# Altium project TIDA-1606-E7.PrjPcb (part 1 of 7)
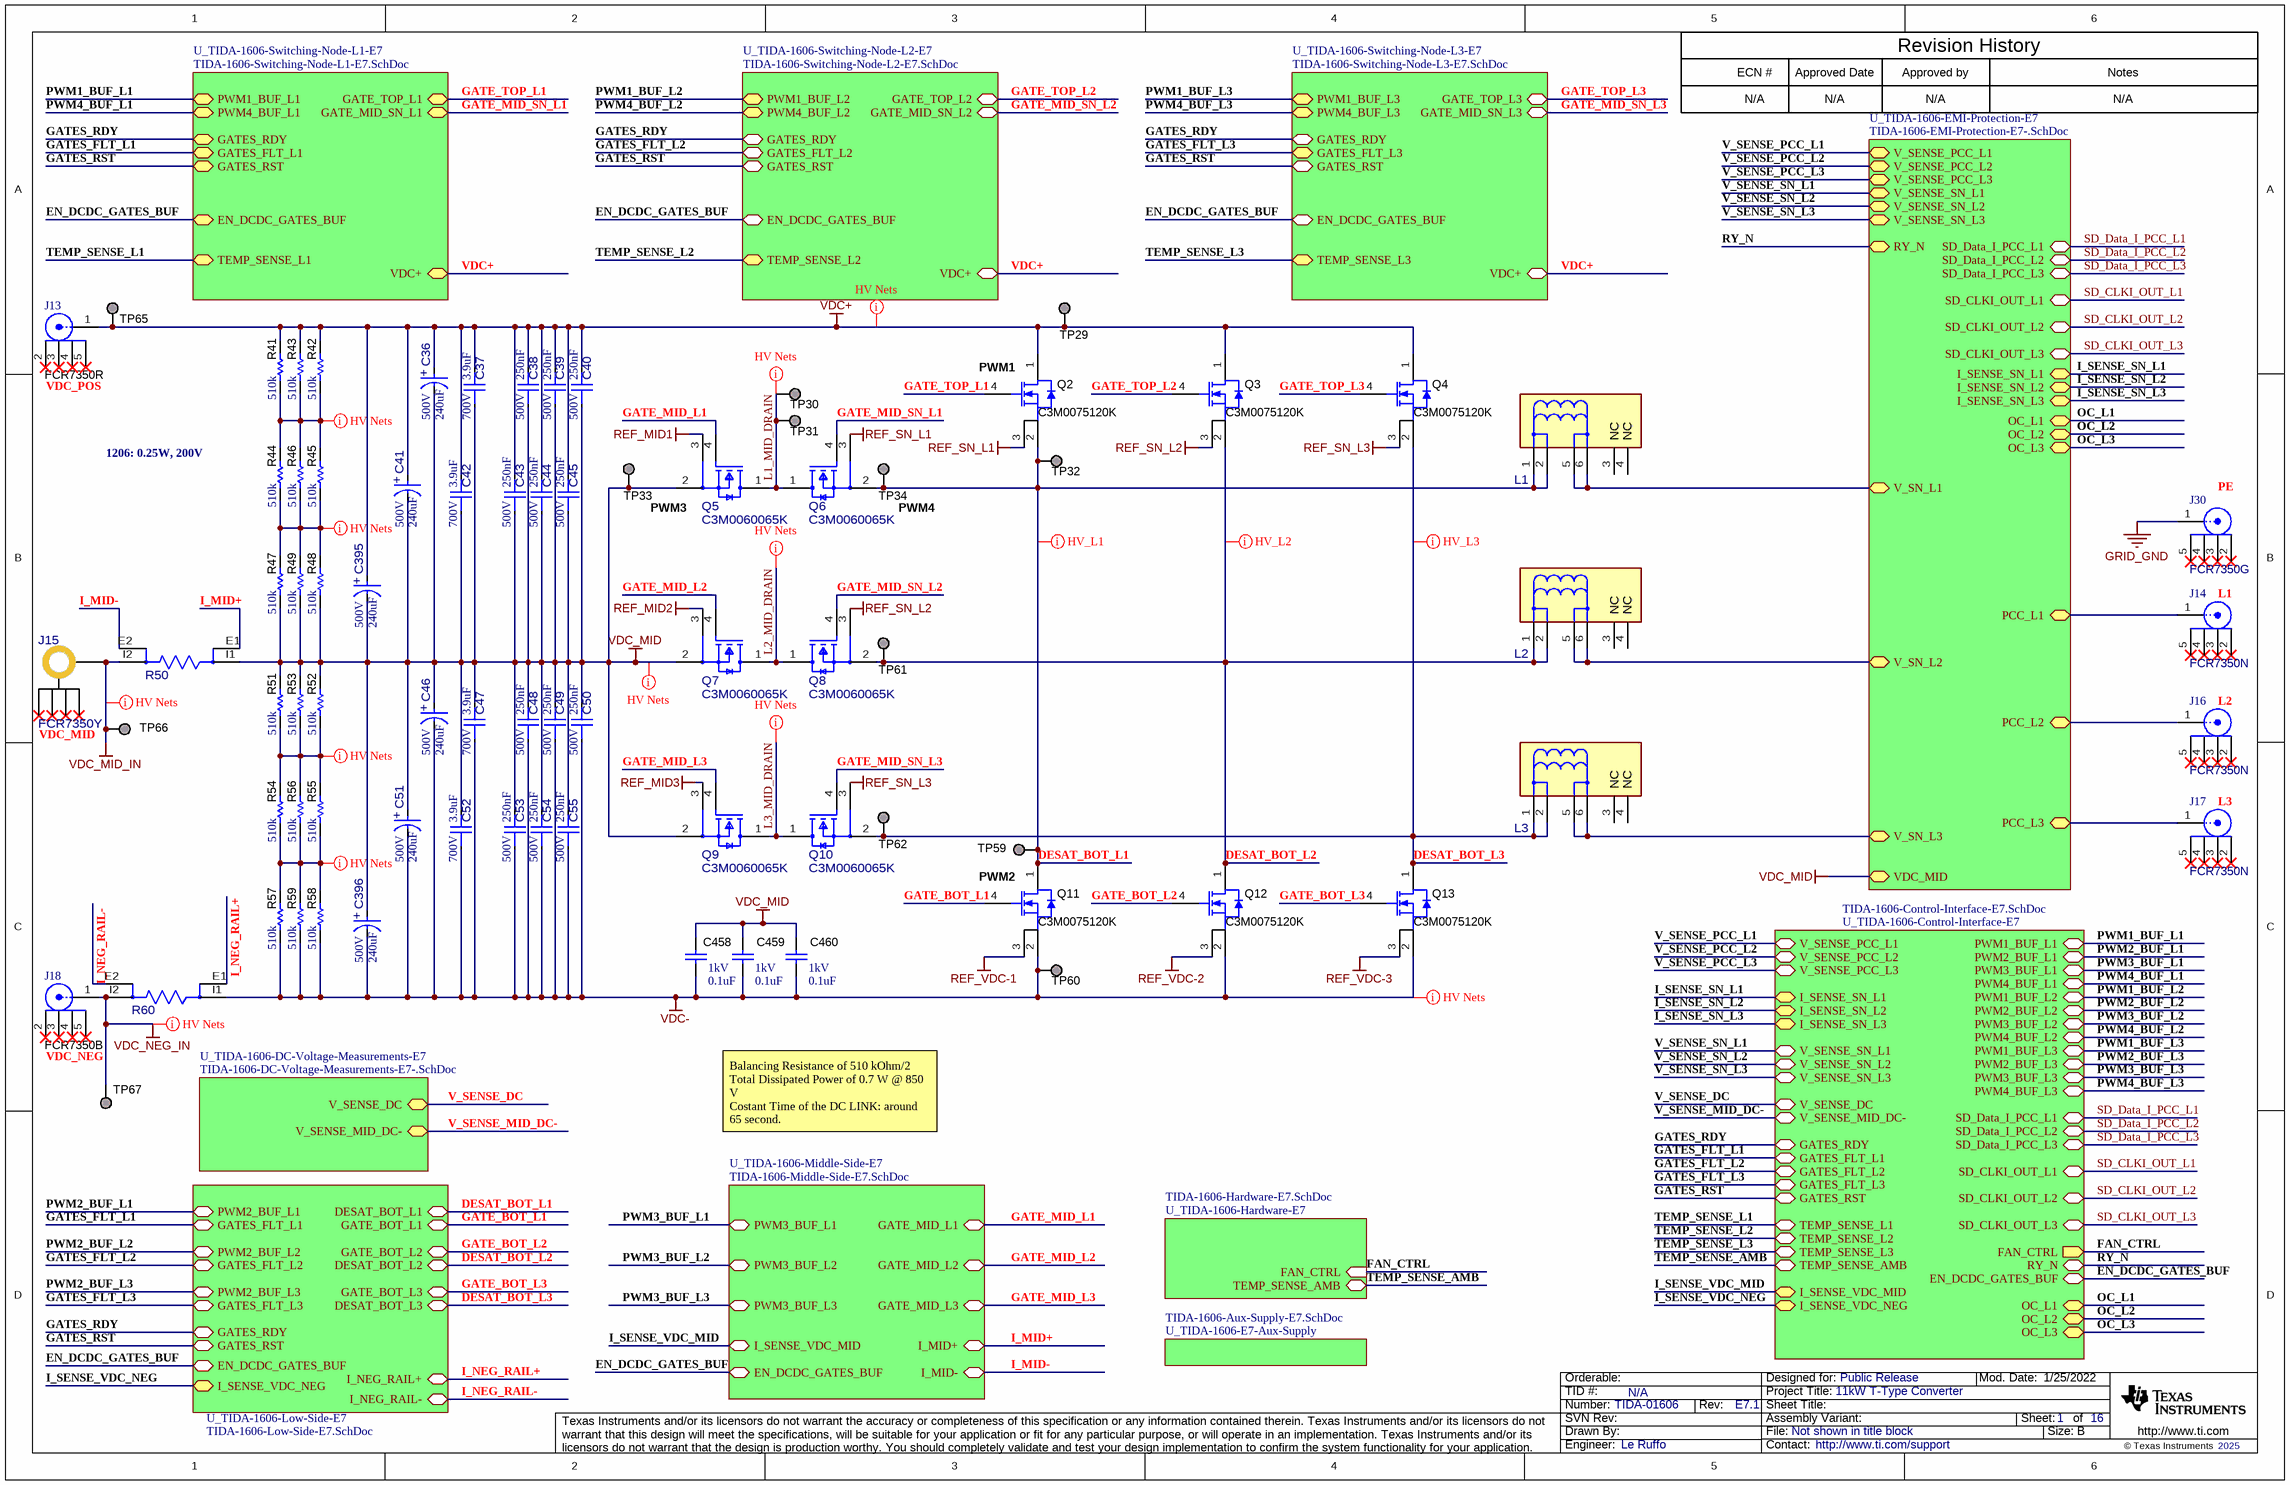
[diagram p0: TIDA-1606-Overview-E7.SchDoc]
TID: N/A; TechSupport: http://www.ti.com/support; SCH_Rev: E7.1; PRJ_Title: 11kW T-Type Converter; PRJ_Number: TIDA-01606; PRJ_Engineer: Le Ruffo; PRJ_Customer: Public Release; PCB_Rev: E7.1; PCB_Layout: Le Ruffo; CopyrightYear: 2025
16 sheets, 1283 parts. Net scope: hierarchical (ports join the sheet entries above them; power ports are global).
Board file: TIDA-1606-E7.PcbDoc
Sheets:
  TIDA-1606-Overview-E7.SchDoc
    U_TIDA-1606-EMI-Protection-E7 = TIDA-1606-EMI-Protection-E7-.SchDoc
      U_TIDA-1606-PCC-Current-Measurements-E7 = TIDA-1606-PCC-Current-Measurements-E7.SchDoc
      U_TIDA-1606-PCC-Voltage-Measurements-E7 = TIDA-1606-PCC-Voltage-Measurements-E7.SchDoc
      U_TIDA-1606-SW-Voltage-Measurements-E7 = TIDA-1606-SW-Voltage-Measurements-E7.SchDoc
      U_TIDA-1606-SW-Current-Measurements-E7 = TIDA-1606-SW-Current-Measurements-E7.SchDoc
    U_TIDA-1606-Switching-Node-L1-E7 = TIDA-1606-Switching-Node-L1-E7.SchDoc
    U_TIDA-1606-Switching-Node-L2-E7 = TIDA-1606-Switching-Node-L2-E7.SchDoc
    U_TIDA-1606-Switching-Node-L3-E7 = TIDA-1606-Switching-Node-L3-E7.SchDoc
    U_TIDA-1606-Low-Side-E7 = TIDA-1606-Low-Side-E7.SchDoc
    U_TIDA-1606-Middle-Side-E7 = TIDA-1606-Middle-Side-E7.SchDoc
    U_TIDA-1606-DC-Voltage-Measurements-E7 = TIDA-1606-DC-Voltage-Measurements-E7-.SchDoc
    U_TIDA-1606-Control-Interface-E7 = TIDA-1606-Control-Interface-E7.SchDoc
      U_TIDA-1606-CAN-Communication-E7 = TIDA-1606-CAN-Communication-E7.SchDoc
    U_TIDA-1606-E7-Aux-Supply = TIDA-1606-Aux-Supply-E7.SchDoc
    U_TIDA-1606-Hardware-E7 = TIDA-1606-Hardware-E7.SchDoc

## Sheet TIDA-1606-Overview-E7.SchDoc
size 431 x 279 mm; Date: Not shown in title block; ApprovedBy: Not shown in title block; CheckedBy: Not shown in title block; Author: Not shown in title block; CompanyName: Not shown in title block; Engineer: Not shown in title block; Organization: Not shown in title block; Address1: Not shown in title block; Address2: Not shown in title block; Address3: Not shown in title block; Address4: Not shown in title block; DocumentNumber: 1; Revision: Use project parameter SCH_Rev; SheetNumber: 1; SheetTotal: 16; PageSetup: Record=PageOptions¦CenterHorizontal=True¦CenterVertical=True¦PrintScale=1.00¦XCorrection=1.00¦YCorrection=1.00¦PrintKind=0¦BorderSize=5000000¦LeftOffset=0¦BottomOffset=0¦Orientation=2¦PaperLength=1000¦PaperWidth=1000¦Scale=100¦PaperSource=15¦PrintQuality=600¦MediaType=1¦DitherType=10¦PaperKind=Letter¦PrintScaleMode=1

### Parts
C36  VDC_V: 500V  ValueDisplayed: 240uF  [FP-ALA8DA241CD500_RADIAL-MFG]  (hidden comment: ALA8DA241CD500)
C37  ValueDisplayed: 3.9uF  VDC_V: 700V  [FP-B32774H8395K000_RADIAL-MFG]  (hidden comment: B32774H8395K000)
C38  ValueDisplayed: 250nF  VDC_V: 500V  [FP-B58043E5254M052_2220-MFG]  (hidden comment: B58043E5254M052)
C39  ValueDisplayed: 250nF  VDC_V: 500V  [FP-B58043E5254M052_2220-MFG]  (hidden comment: B58043E5254M052)
C40  ValueDisplayed: 250nF  VDC_V: 500V  [FP-B58043E5254M052_2220-MFG]  (hidden comment: B58043E5254M052)
C41  VDC_V: 500V  ValueDisplayed: 240uF  [FP-ALA8DA241CD500_RADIAL-MFG]  (hidden comment: ALA8DA241CD500)
C42  ValueDisplayed: 3.9uF  VDC_V: 700V  [FP-B32774H8395K000_RADIAL-MFG]  (hidden comment: B32774H8395K000)
C43  ValueDisplayed: 250nF  VDC_V: 500V  [FP-B58043E5254M052_2220-MFG]  (hidden comment: B58043E5254M052)
C44  ValueDisplayed: 250nF  VDC_V: 500V  [FP-B58043E5254M052_2220-MFG]  (hidden comment: B58043E5254M052)
C45  ValueDisplayed: 250nF  VDC_V: 500V  [FP-B58043E5254M052_2220-MFG]  (hidden comment: B58043E5254M052)
C46  VDC_V: 500V  ValueDisplayed: 240uF  [FP-ALA8DA241CD500_RADIAL-MFG]  (hidden comment: ALA8DA241CD500)
C47  ValueDisplayed: 3.9uF  VDC_V: 700V  [FP-B32774H8395K000_RADIAL-MFG]  (hidden comment: B32774H8395K000)
C48  ValueDisplayed: 250nF  VDC_V: 500V  [FP-B58043E5254M052_2220-MFG]  (hidden comment: B58043E5254M052)
C49  ValueDisplayed: 250nF  VDC_V: 500V  [FP-B58043E5254M052_2220-MFG]  (hidden comment: B58043E5254M052)
C50  ValueDisplayed: 250nF  VDC_V: 500V  [FP-B58043E5254M052_2220-MFG]  (hidden comment: B58043E5254M052)
C51  VDC_V: 500V  ValueDisplayed: 240uF  [FP-ALA8DA241CD500_RADIAL-MFG]  (hidden comment: ALA8DA241CD500)
C52  ValueDisplayed: 3.9uF  VDC_V: 700V  [FP-B32774H8395K000_RADIAL-MFG]  (hidden comment: B32774H8395K000)
C53  ValueDisplayed: 250nF  VDC_V: 500V  [FP-B58043E5254M052_2220-MFG]  (hidden comment: B58043E5254M052)
C54  ValueDisplayed: 250nF  VDC_V: 500V  [FP-B58043E5254M052_2220-MFG]  (hidden comment: B58043E5254M052)
C55  ValueDisplayed: 250nF  VDC_V: 500V  [FP-B58043E5254M052_2220-MFG]  (hidden comment: B58043E5254M052)
C395  VDC_V: 500V  ValueDisplayed: 240uF  [FP-ALA8DA241CD500_RADIAL-MFG]  (hidden comment: ALA8DA241CD500)
C396  VDC_V: 500V  ValueDisplayed: 240uF  [FP-ALA8DA241CD500_RADIAL-MFG]  (hidden comment: ALA8DA241CD500)
C458  VDC_V: 1kV  ValueDisplayed: 0.1uF  [1812_254]  (hidden comment: C1812W104KDRACTU)
C459  VDC_V: 1kV  ValueDisplayed: 0.1uF  [1812_254]  (hidden comment: C1812W104KDRACTU)
C460  VDC_V: 1kV  ValueDisplayed: 0.1uF  [1812_254]  (hidden comment: C1812W104KDRACTU)
J13  FCR7350R  [Cliff_FCR7350R]
J14  FCR7350N  [FP-FCR7350N_CONN_BANANA_JACK-MFG]
J15  FCR7350Y  [FP-FCR7350Y_CONN_BANANA_JACK-MFG]
J16  FCR7350N  [FP-FCR7350N_CONN_BANANA_JACK-MFG]
J17  FCR7350N  [FP-FCR7350N_CONN_BANANA_JACK-MFG]
J18  FCR7350B  [Cliff_FCR7350B]
J30  FCR7350G  [FP-FCR7350G_CONN_BANANA_JACK-MFG]
L1  B181108 D6665 V2  [FP-B181108 D6665 V2_PTH_IND_52MM5_59MM0-MFG]  (value not drawn)
L2  B181108 D6665 V2  [FP-B181108 D6665 V2_PTH_IND_52MM5_59MM0-MFG]  (value not drawn)
L3  B181108 D6665 V2  [FP-B181108 D6665 V2_PTH_IND_52MM5_59MM0-MFG]  (value not drawn)
Q2  C3M0075120K  [TO-247-4]
Q3  C3M0075120K  [TO-247-4]
Q4  C3M0075120K  [TO-247-4]
Q5  C3M0060065K  [FP-C3M0060065K_TO-247-4L-MFG]
Q6  C3M0060065K  [FP-C3M0060065K_TO-247-4L-MFG]
Q7  C3M0060065K  [FP-C3M0060065K_TO-247-4L-MFG]
Q8  C3M0060065K  [FP-C3M0060065K_TO-247-4L-MFG]
Q9  C3M0060065K  [FP-C3M0060065K_TO-247-4L-MFG]
Q10  C3M0060065K  [FP-C3M0060065K_TO-247-4L-MFG]
Q11  C3M0075120K  [TO-247-4]
Q12  C3M0075120K  [TO-247-4]
Q13  C3M0075120K  [TO-247-4]
R41  ValueDisplayed: 510k  [1206]  (hidden comment: CRCW1206510KJNEA)
R42  ValueDisplayed: 510k  [1206]  (hidden comment: CRCW1206510KJNEA)
R43  ValueDisplayed: 510k  [1206]  (hidden comment: CRCW1206510KJNEA)
R44  ValueDisplayed: 510k  [1206]  (hidden comment: CRCW1206510KJNEA)
R45  ValueDisplayed: 510k  [1206]  (hidden comment: CRCW1206510KJNEA)
R46  ValueDisplayed: 510k  [1206]  (hidden comment: CRCW1206510KJNEA)
R47  ValueDisplayed: 510k  [1206]  (hidden comment: CRCW1206510KJNEA)
R48  ValueDisplayed: 510k  [1206]  (hidden comment: CRCW1206510KJNEA)
R49  ValueDisplayed: 510k  [1206]  (hidden comment: CRCW1206510KJNEA)
R50  WSKW06122L000FEA  [FP-WSKW06122L000FEA_0612-MFG]  (value not drawn)
R51  ValueDisplayed: 510k  [1206]  (hidden comment: CRCW1206510KJNEA)
R52  ValueDisplayed: 510k  [1206]  (hidden comment: CRCW1206510KJNEA)
R53  ValueDisplayed: 510k  [1206]  (hidden comment: CRCW1206510KJNEA)
R54  ValueDisplayed: 510k  [1206]  (hidden comment: CRCW1206510KJNEA)
R55  ValueDisplayed: 510k  [1206]  (hidden comment: CRCW1206510KJNEA)
R56  ValueDisplayed: 510k  [1206]  (hidden comment: CRCW1206510KJNEA)
R57  ValueDisplayed: 510k  [1206]  (hidden comment: CRCW1206510KJNEA)
R58  ValueDisplayed: 510k  [1206]  (hidden comment: CRCW1206510KJNEA)
R59  ValueDisplayed: 510k  [1206]  (hidden comment: CRCW1206510KJNEA)
R60  WSKW06122L000FEA  [FP-WSKW06122L000FEA_0612-MFG]  (value not drawn)
TP29  S2751-46R  [Harwin_S2751-46R]  (value not drawn)
TP30  S2751-46R  [Harwin_S2751-46R]  (value not drawn)
TP31  S2751-46R  [Harwin_S2751-46R]  (value not drawn)
TP32  S2751-46R  [Harwin_S2751-46R]  (value not drawn)
TP33  S2751-46R  [Harwin_S2751-46R]  (value not drawn)
TP34  S2751-46R  [Harwin_S2751-46R]  (value not drawn)
TP59  S2751-46R  [Harwin_S2751-46R]  (value not drawn)
TP60  S2751-46R  [Harwin_S2751-46R]  (value not drawn)
TP61  S2751-46R  [Harwin_S2751-46R]  (value not drawn)
TP62  S2751-46R  [Harwin_S2751-46R]  (value not drawn)
TP65  S2751-46R  [Harwin_S2751-46R]  (value not drawn)
TP66  S2751-46R  [Harwin_S2751-46R]  (value not drawn)
TP67  S2751-46R  [Harwin_S2751-46R]  (value not drawn)

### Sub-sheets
U_TIDA-1606-Control-Interface-E7 = TIDA-1606-Control-Interface-E7.SchDoc: PWM1_BUF_L1 (bidir), PWM2_BUF_L1 (bidir), PWM3_BUF_L1 (bidir), PWM4_BUF_L1 (bidir), PWM1_BUF_L2 (bidir), PWM2_BUF_L2 (bidir), PWM3_BUF_L2 (bidir), PWM4_BUF_L2 (bidir), PWM1_BUF_L3 (bidir), PWM2_BUF_L3 (bidir), PWM3_BUF_L3 (bidir), PWM4_BUF_L3 (bidir), TEMP_SENSE_L1 (bidir), TEMP_SENSE_L2 (bidir), TEMP_SENSE_L3 (bidir), TEMP_SENSE_AMB (bidir), V_SENSE_PCC_L3 (bidir), V_SENSE_SN_L3 (bidir), V_SENSE_MID_DC- (bidir), V_SENSE_DC (bidir), V_SENSE_PCC_L1 (bidir), V_SENSE_SN_L1 (bidir), V_SENSE_PCC_L2 (bidir), V_SENSE_SN_L2 (bidir), GATES_FLT_L1 (bidir), GATES_FLT_L2 (bidir), GATES_FLT_L3 (bidir), GATES_RST (bidir), RY_N (bidir), EN_DCDC_GATES_BUF (bidir), GATES_RDY (bidir), I_SENSE_VDC_MID (bidir), I_SENSE_VDC_NEG (bidir), FAN_CTRL (out), OC_L1 (bidir), OC_L2 (bidir), OC_L3 (bidir), I_SENSE_SN_L1 (bidir), I_SENSE_SN_L2 (bidir), I_SENSE_SN_L3 (bidir), SD_Data_I_PCC_L1 (bidir), SD_Data_I_PCC_L2 (bidir), SD_Data_I_PCC_L3 (bidir), SD_CLKI_OUT_L1 (bidir), SD_CLKI_OUT_L2 (bidir), SD_CLKI_OUT_L3 (bidir)
U_TIDA-1606-DC-Voltage-Measurements-E7 = TIDA-1606-DC-Voltage-Measurements-E7-.SchDoc: V_SENSE_MID_DC- (bidir), V_SENSE_DC (bidir)
U_TIDA-1606-E7-Aux-Supply = TIDA-1606-Aux-Supply-E7.SchDoc: no entries
U_TIDA-1606-EMI-Protection-E7 = TIDA-1606-EMI-Protection-E7-.SchDoc: VDC_MID (bidir), V_SN_L1 (bidir), V_SN_L2 (bidir), V_SN_L3 (bidir), PCC_L1 (bidir), PCC_L2 (bidir), PCC_L3 (bidir), V_SENSE_PCC_L3 (bidir), V_SENSE_PCC_L2 (bidir), V_SENSE_SN_L1 (bidir), V_SENSE_PCC_L1 (bidir), V_SENSE_SN_L2 (bidir), V_SENSE_SN_L3 (bidir), RY_N (bidir), SD_Data_I_PCC_L1 (bidir), SD_Data_I_PCC_L2 (bidir), SD_Data_I_PCC_L3 (bidir), SD_CLKI_OUT_L1 (bidir), SD_CLKI_OUT_L2 (bidir), SD_CLKI_OUT_L3 (bidir), I_SENSE_SN_L1 (bidir), I_SENSE_SN_L2 (bidir), I_SENSE_SN_L3 (bidir), OC_L1 (bidir), OC_L2 (bidir), OC_L3 (bidir)
U_TIDA-1606-Hardware-E7 = TIDA-1606-Hardware-E7.SchDoc: FAN_CTRL (in), TEMP_SENSE_AMB (bidir)
U_TIDA-1606-Low-Side-E7 = TIDA-1606-Low-Side-E7.SchDoc: EN_DCDC_GATES_BUF (bidir), PWM2_BUF_L1 (bidir), GATES_RDY (bidir), GATES_FLT_L1 (bidir), GATES_RST (bidir), GATES_FLT_L2 (bidir), GATES_FLT_L3 (bidir), PWM2_BUF_L2 (bidir), PWM2_BUF_L3 (bidir), DESAT_BOT_L1 (bidir), DESAT_BOT_L2 (bidir), DESAT_BOT_L3 (bidir), GATE_BOT_L1 (bidir), GATE_BOT_L2 (bidir), GATE_BOT_L3 (bidir), I_NEG_RAIL+ (bidir), I_NEG_RAIL- (bidir), I_SENSE_VDC_NEG (bidir)
U_TIDA-1606-Middle-Side-E7 = TIDA-1606-Middle-Side-E7.SchDoc: I_SENSE_VDC_MID (bidir), PWM3_BUF_L3 (bidir), PWM3_BUF_L2 (bidir), PWM3_BUF_L1 (bidir), EN_DCDC_GATES_BUF (bidir), I_MID- (bidir), I_MID+ (bidir), GATE_MID_L3 (bidir), GATE_MID_L2 (bidir), GATE_MID_L1 (bidir)
U_TIDA-1606-Switching-Node-L1-E7 = TIDA-1606-Switching-Node-L1-E7.SchDoc: GATE_TOP_L1 (bidir), GATES_RDY (bidir), GATES_FLT_L1 (bidir), EN_DCDC_GATES_BUF (bidir), VDC+ (bidir), GATES_RST (bidir), GATE_MID_SN_L1 (bidir), PWM4_BUF_L1 (bidir), PWM1_BUF_L1 (bidir), TEMP_SENSE_L1 (bidir)
U_TIDA-1606-Switching-Node-L2-E7 = TIDA-1606-Switching-Node-L2-E7.SchDoc: VDC+ (bidir), GATE_TOP_L2 (bidir), GATE_MID_SN_L2 (bidir), EN_DCDC_GATES_BUF (bidir), GATES_RDY (bidir), GATES_FLT_L2 (bidir), GATES_RST (bidir), PWM4_BUF_L2 (bidir), PWM1_BUF_L2 (bidir), TEMP_SENSE_L2 (bidir)
U_TIDA-1606-Switching-Node-L3-E7 = TIDA-1606-Switching-Node-L3-E7.SchDoc: VDC+ (bidir), GATE_TOP_L3 (bidir), GATE_MID_SN_L3 (bidir), EN_DCDC_GATES_BUF (bidir), GATES_RDY (bidir), GATES_RST (bidir), GATES_FLT_L3 (bidir), PWM4_BUF_L3 (bidir), PWM1_BUF_L3 (bidir), TEMP_SENSE_L3 (bidir)

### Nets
GRID_GND: J30.1
REF_MID1: Q5.3(Driver_Source)
REF_MID2: Q7.3(Driver_Source)
REF_MID3: Q9.3(Driver_Source)
REF_SN_L1: Q2.3(KS) Q6.3(Driver_Source)
REF_SN_L2: Q3.3(KS) Q8.3(Driver_Source)
REF_SN_L3: Q4.3(KS) Q10.3(Driver_Source)
REF_VDC-1: Q11.3(KS)
REF_VDC-2: Q12.3(KS)
REF_VDC-3: Q13.3(KS)
VDC+: C36.2(ANODE) C37.2 C38.2 C39.2 C40.2 C41.2(ANODE) C42.2 C43.2 C44.2 C45.2 C395.2(ANODE) J13.1 Q2.1(D) Q3.1(D) Q4.1(D) R41.2 R42.2 R43.2 TP29.1 TP65.1 ; sheet U_TIDA-1606-Switching-Node-L1-E7/VDC+, sheet U_TIDA-1606-Switching-Node-L2-E7/VDC+, sheet U_TIDA-1606-Switching-Node-L3-E7/VDC+
VDC-: C46.1(CATHODE) C47.1 C48.1 C49.1 C50.1 C51.1(CATHODE) C52.1 C53.1 C54.1 C55.1 C396.1(CATHODE) C458.1 C459.1 C460.1 Q11.2(S) Q12.2(S) Q13.2(S) R57.1 R58.1 R59.1 R60.I1 TP60.1
VDC_MID: C36.1(CATHODE) C37.1 C38.1 C39.1 C40.1 C41.1(CATHODE) C42.1 C43.1 C44.1 C45.1 C46.2(ANODE) C47.2 C48.2 C49.2 C50.2 C51.2(ANODE) C52.2 C53.2 C54.2 C55.2 C395.1(CATHODE) C396.2(ANODE) C458.2 C459.2 C460.2 Q5.2(Power_Source) Q7.2(Power_Source) Q9.2(Power_Source) R47.1 R48.1 R49.1 R50.I1 R51.2 R52.2 R53.2 TP33.1 ; sheet U_TIDA-1606-EMI-Protection-E7/VDC_MID
VDC_MID_IN: J15.1 R50.I2 TP66.1
VDC_NEG_IN: J18.1 R60.I2 TP67.1
DESAT_BOT_L1: L1.1 L1.2 Q2.2(S) Q6.2(Power_Source) Q11.1(D) TP32.1 TP34.1 TP59.1 ; sheet U_TIDA-1606-Low-Side-E7/DESAT_BOT_L1
DESAT_BOT_L2: L2.1 L2.2 Q3.2(S) Q8.2(Power_Source) Q12.1(D) TP61.1 ; sheet U_TIDA-1606-Low-Side-E7/DESAT_BOT_L2
DESAT_BOT_L3: L3.1 L3.2 Q4.2(S) Q10.2(Power_Source) Q13.1(D) TP62.1 ; sheet U_TIDA-1606-Low-Side-E7/DESAT_BOT_L3
EN_DCDC_GATES_BUF: sheet U_TIDA-1606-Switching-Node-L1-E7/EN_DCDC_GATES_BUF, sheet U_TIDA-1606-Switching-Node-L2-E7/EN_DCDC_GATES_BUF, sheet U_TIDA-1606-Switching-Node-L3-E7/EN_DCDC_GATES_BUF, sheet U_TIDA-1606-Low-Side-E7/EN_DCDC_GATES_BUF, sheet U_TIDA-1606-Middle-Side-E7/EN_DCDC_GATES_BUF, sheet U_TIDA-1606-Control-Interface-E7/EN_DCDC_GATES_BUF
FAN_CTRL: sheet U_TIDA-1606-Control-Interface-E7/FAN_CTRL, sheet U_TIDA-1606-Hardware-E7/FAN_CTRL
GATE_BOT_L1: Q11.4(G) ; sheet U_TIDA-1606-Low-Side-E7/GATE_BOT_L1
GATE_BOT_L2: Q12.4(G) ; sheet U_TIDA-1606-Low-Side-E7/GATE_BOT_L2
GATE_BOT_L3: Q13.4(G) ; sheet U_TIDA-1606-Low-Side-E7/GATE_BOT_L3
GATE_MID_L1: Q5.4(Gate) ; sheet U_TIDA-1606-Middle-Side-E7/GATE_MID_L1
GATE_MID_L2: Q7.4(Gate) ; sheet U_TIDA-1606-Middle-Side-E7/GATE_MID_L2
GATE_MID_L3: Q9.4(Gate) ; sheet U_TIDA-1606-Middle-Side-E7/GATE_MID_L3
GATE_MID_SN_L1: Q6.4(Gate) ; sheet U_TIDA-1606-Switching-Node-L1-E7/GATE_MID_SN_L1
GATE_MID_SN_L2: Q8.4(Gate) ; sheet U_TIDA-1606-Switching-Node-L2-E7/GATE_MID_SN_L2
GATE_MID_SN_L3: Q10.4(Gate) ; sheet U_TIDA-1606-Switching-Node-L3-E7/GATE_MID_SN_L3
GATE_TOP_L1: Q2.4(G) ; sheet U_TIDA-1606-Switching-Node-L1-E7/GATE_TOP_L1
GATE_TOP_L2: Q3.4(G) ; sheet U_TIDA-1606-Switching-Node-L2-E7/GATE_TOP_L2
GATE_TOP_L3: Q4.4(G) ; sheet U_TIDA-1606-Switching-Node-L3-E7/GATE_TOP_L3
GATES_FLT_L1: sheet U_TIDA-1606-Switching-Node-L1-E7/GATES_FLT_L1, sheet U_TIDA-1606-Low-Side-E7/GATES_FLT_L1, sheet U_TIDA-1606-Control-Interface-E7/GATES_FLT_L1
GATES_FLT_L2: sheet U_TIDA-1606-Switching-Node-L2-E7/GATES_FLT_L2, sheet U_TIDA-1606-Low-Side-E7/GATES_FLT_L2, sheet U_TIDA-1606-Control-Interface-E7/GATES_FLT_L2
GATES_FLT_L3: sheet U_TIDA-1606-Switching-Node-L3-E7/GATES_FLT_L3, sheet U_TIDA-1606-Low-Side-E7/GATES_FLT_L3, sheet U_TIDA-1606-Control-Interface-E7/GATES_FLT_L3
GATES_RDY: sheet U_TIDA-1606-Switching-Node-L1-E7/GATES_RDY, sheet U_TIDA-1606-Switching-Node-L2-E7/GATES_RDY, sheet U_TIDA-1606-Switching-Node-L3-E7/GATES_RDY, sheet U_TIDA-1606-Low-Side-E7/GATES_RDY, sheet U_TIDA-1606-Control-Interface-E7/GATES_RDY
GATES_RST: sheet U_TIDA-1606-Switching-Node-L1-E7/GATES_RST, sheet U_TIDA-1606-Switching-Node-L2-E7/GATES_RST, sheet U_TIDA-1606-Switching-Node-L3-E7/GATES_RST, sheet U_TIDA-1606-Low-Side-E7/GATES_RST, sheet U_TIDA-1606-Control-Interface-E7/GATES_RST
I_MID+: R50.E1 ; sheet U_TIDA-1606-Middle-Side-E7/I_MID+
I_MID-: R50.E2 ; sheet U_TIDA-1606-Middle-Side-E7/I_MID-
I_NEG_RAIL+: R60.E1 ; sheet U_TIDA-1606-Low-Side-E7/I_NEG_RAIL+
I_NEG_RAIL-: R60.E2 ; sheet U_TIDA-1606-Low-Side-E7/I_NEG_RAIL-
I_SENSE_SN_L1: sheet U_TIDA-1606-EMI-Protection-E7/I_SENSE_SN_L1, sheet U_TIDA-1606-Control-Interface-E7/I_SENSE_SN_L1
I_SENSE_SN_L2: sheet U_TIDA-1606-EMI-Protection-E7/I_SENSE_SN_L2, sheet U_TIDA-1606-Control-Interface-E7/I_SENSE_SN_L2
I_SENSE_SN_L3: sheet U_TIDA-1606-EMI-Protection-E7/I_SENSE_SN_L3, sheet U_TIDA-1606-Control-Interface-E7/I_SENSE_SN_L3
I_SENSE_VDC_MID: sheet U_TIDA-1606-Middle-Side-E7/I_SENSE_VDC_MID, sheet U_TIDA-1606-Control-Interface-E7/I_SENSE_VDC_MID
I_SENSE_VDC_NEG: sheet U_TIDA-1606-Low-Side-E7/I_SENSE_VDC_NEG, sheet U_TIDA-1606-Control-Interface-E7/I_SENSE_VDC_NEG
I_SN_L1+: L1.5 L1.6 ; sheet U_TIDA-1606-EMI-Protection-E7/V_SN_L1
I_SN_L2+: L2.5 L2.6 ; sheet U_TIDA-1606-EMI-Protection-E7/V_SN_L2
I_SN_L3+: L3.5 L3.6 ; sheet U_TIDA-1606-EMI-Protection-E7/V_SN_L3
L1_MID_DRAIN: Q5.1(Drain) Q6.1(Drain) TP30.1 TP31.1
L2_MID_DRAIN: Q7.1(Drain) Q8.1(Drain)
L3_MID_DRAIN: Q9.1(Drain) Q10.1(Drain)
OC_L1: sheet U_TIDA-1606-EMI-Protection-E7/OC_L1, sheet U_TIDA-1606-Control-Interface-E7/OC_L1
OC_L2: sheet U_TIDA-1606-EMI-Protection-E7/OC_L2, sheet U_TIDA-1606-Control-Interface-E7/OC_L2
OC_L3: sheet U_TIDA-1606-EMI-Protection-E7/OC_L3, sheet U_TIDA-1606-Control-Interface-E7/OC_L3
PCC_L1: J14.1 ; sheet U_TIDA-1606-EMI-Protection-E7/PCC_L1
PCC_L2: J16.1 ; sheet U_TIDA-1606-EMI-Protection-E7/PCC_L2
PCC_L3: J17.1 ; sheet U_TIDA-1606-EMI-Protection-E7/PCC_L3
PWM1_BUF_L1: sheet U_TIDA-1606-Switching-Node-L1-E7/PWM1_BUF_L1, sheet U_TIDA-1606-Control-Interface-E7/PWM1_BUF_L1
PWM1_BUF_L2: sheet U_TIDA-1606-Switching-Node-L2-E7/PWM1_BUF_L2, sheet U_TIDA-1606-Control-Interface-E7/PWM1_BUF_L2
PWM1_BUF_L3: sheet U_TIDA-1606-Switching-Node-L3-E7/PWM1_BUF_L3, sheet U_TIDA-1606-Control-Interface-E7/PWM1_BUF_L3
PWM2_BUF_L1: sheet U_TIDA-1606-Low-Side-E7/PWM2_BUF_L1, sheet U_TIDA-1606-Control-Interface-E7/PWM2_BUF_L1
PWM2_BUF_L2: sheet U_TIDA-1606-Low-Side-E7/PWM2_BUF_L2, sheet U_TIDA-1606-Control-Interface-E7/PWM2_BUF_L2
PWM2_BUF_L3: sheet U_TIDA-1606-Low-Side-E7/PWM2_BUF_L3, sheet U_TIDA-1606-Control-Interface-E7/PWM2_BUF_L3
PWM3_BUF_L1: sheet U_TIDA-1606-Middle-Side-E7/PWM3_BUF_L1, sheet U_TIDA-1606-Control-Interface-E7/PWM3_BUF_L1
PWM3_BUF_L2: sheet U_TIDA-1606-Middle-Side-E7/PWM3_BUF_L2, sheet U_TIDA-1606-Control-Interface-E7/PWM3_BUF_L2
PWM3_BUF_L3: sheet U_TIDA-1606-Middle-Side-E7/PWM3_BUF_L3, sheet U_TIDA-1606-Control-Interface-E7/PWM3_BUF_L3
PWM4_BUF_L1: sheet U_TIDA-1606-Switching-Node-L1-E7/PWM4_BUF_L1, sheet U_TIDA-1606-Control-Interface-E7/PWM4_BUF_L1
PWM4_BUF_L2: sheet U_TIDA-1606-Switching-Node-L2-E7/PWM4_BUF_L2, sheet U_TIDA-1606-Control-Interface-E7/PWM4_BUF_L2
PWM4_BUF_L3: sheet U_TIDA-1606-Switching-Node-L3-E7/PWM4_BUF_L3, sheet U_TIDA-1606-Control-Interface-E7/PWM4_BUF_L3
RY_N: sheet U_TIDA-1606-EMI-Protection-E7/RY_N, sheet U_TIDA-1606-Control-Interface-E7/RY_N
SD_CLKI_OUT_L1: sheet U_TIDA-1606-EMI-Protection-E7/SD_CLKI_OUT_L1, sheet U_TIDA-1606-Control-Interface-E7/SD_CLKI_OUT_L1
SD_CLKI_OUT_L2: sheet U_TIDA-1606-EMI-Protection-E7/SD_CLKI_OUT_L2, sheet U_TIDA-1606-Control-Interface-E7/SD_CLKI_OUT_L2
SD_CLKI_OUT_L3: sheet U_TIDA-1606-EMI-Protection-E7/SD_CLKI_OUT_L3, sheet U_TIDA-1606-Control-Interface-E7/SD_CLKI_OUT_L3
SD_Data_I_PCC_L1: sheet U_TIDA-1606-EMI-Protection-E7/SD_Data_I_PCC_L1, sheet U_TIDA-1606-Control-Interface-E7/SD_Data_I_PCC_L1
SD_Data_I_PCC_L2: sheet U_TIDA-1606-EMI-Protection-E7/SD_Data_I_PCC_L2, sheet U_TIDA-1606-Control-Interface-E7/SD_Data_I_PCC_L2
SD_Data_I_PCC_L3: sheet U_TIDA-1606-EMI-Protection-E7/SD_Data_I_PCC_L3, sheet U_TIDA-1606-Control-Interface-E7/SD_Data_I_PCC_L3
TEMP_SENSE_AMB: sheet U_TIDA-1606-Control-Interface-E7/TEMP_SENSE_AMB, sheet U_TIDA-1606-Hardware-E7/TEMP_SENSE_AMB
TEMP_SENSE_L1: sheet U_TIDA-1606-Switching-Node-L1-E7/TEMP_SENSE_L1, sheet U_TIDA-1606-Control-Interface-E7/TEMP_SENSE_L1
TEMP_SENSE_L2: sheet U_TIDA-1606-Switching-Node-L2-E7/TEMP_SENSE_L2, sheet U_TIDA-1606-Control-Interface-E7/TEMP_SENSE_L2
TEMP_SENSE_L3: sheet U_TIDA-1606-Switching-Node-L3-E7/TEMP_SENSE_L3, sheet U_TIDA-1606-Control-Interface-E7/TEMP_SENSE_L3
V_SENSE_DC: sheet U_TIDA-1606-DC-Voltage-Measurements-E7/V_SENSE_DC, sheet U_TIDA-1606-Control-Interface-E7/V_SENSE_DC
V_SENSE_MID_DC-: sheet U_TIDA-1606-DC-Voltage-Measurements-E7/V_SENSE_MID_DC-, sheet U_TIDA-1606-Control-Interface-E7/V_SENSE_MID_DC-
V_SENSE_PCC_L1: sheet U_TIDA-1606-EMI-Protection-E7/V_SENSE_PCC_L1, sheet U_TIDA-1606-Control-Interface-E7/V_SENSE_PCC_L1
V_SENSE_PCC_L2: sheet U_TIDA-1606-EMI-Protection-E7/V_SENSE_PCC_L2, sheet U_TIDA-1606-Control-Interface-E7/V_SENSE_PCC_L2
V_SENSE_PCC_L3: sheet U_TIDA-1606-EMI-Protection-E7/V_SENSE_PCC_L3, sheet U_TIDA-1606-Control-Interface-E7/V_SENSE_PCC_L3
V_SENSE_SN_L1: sheet U_TIDA-1606-EMI-Protection-E7/V_SENSE_SN_L1, sheet U_TIDA-1606-Control-Interface-E7/V_SENSE_SN_L1
V_SENSE_SN_L2: sheet U_TIDA-1606-EMI-Protection-E7/V_SENSE_SN_L2, sheet U_TIDA-1606-Control-Interface-E7/V_SENSE_SN_L2
V_SENSE_SN_L3: sheet U_TIDA-1606-EMI-Protection-E7/V_SENSE_SN_L3, sheet U_TIDA-1606-Control-Interface-E7/V_SENSE_SN_L3
NetR41_1: R41.1 R42.1 R43.1 R44.2 R45.2 R46.2
NetR44_1: R44.1 R45.1 R46.1 R47.2 R48.2 R49.2
NetR51_1: R51.1 R52.1 R53.1 R54.2 R55.2 R56.2
NetR54_1: R54.1 R55.1 R56.1 R57.2 R58.2 R59.2

Not connected (* = marked no-connect by the designer): J13 2* 3* 4* 5*; J14 2* 3* 4* 5*; J15 2(MNT_1)* 3(MNT_2)* 4(MNT_3)* 5(MNT_4)*; J16 2* 3* 4* 5*; J17 2* 3* 4* 5*; J18 2* 3* 4* 5*; J30 2* 3* 4* 5*; L1 3(NC) 4(NC); L2 3(NC) 4(NC); L3 3(NC) 4(NC)

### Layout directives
net class HV_Nets: L1_MID_DRAIN, L2_MID_DRAIN, L3_MID_DRAIN, NetR41_1, NetR44_1, NetR51_1, NetR54_1, VDC+
net class HV_Nets; net class HV_VDC_LOW: VDC-, VDC_NEG_IN
net class HV_Nets; net class HV_VDC_MID: VDC_MID, VDC_MID_IN
net class HV_L1; net class HV_Nets: DESAT_BOT_L1
net class HV_L2; net class HV_Nets: DESAT_BOT_L2
net class HV_L3; net class HV_Nets: DESAT_BOT_L3

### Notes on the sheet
- ECN #
- N/A
- Approved Date
- Approved by
- Revision History
- Notes
- (near Q2) PWM1
- (near J13) VDC_POS
- 1206: 0.25W, 200V
- (near J30) PE
- PWM3
- (near TP34) PWM4
- (near J14) L1
- (near J16) L2
- VDC_MID
- (near J17) L3
- (near Q11) PWM2
- VDC_NEG
- Balancing Resistance of 510 kOhm/2
  Total Dissipated Power of 0.7 W @ 850 V
  Costant Time of the DC LINK: around 65 second.

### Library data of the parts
C36 C41 C46 C51 C395 C396 = CMP-0097092-1: 240 µF 500 V Aluminum Electrolytic Capacitors Radial, Can - Snap-In 859.2mOhm @ 100Hz 7000 Hrs @ 105°C; Manufacturer: KEMET; Tolerance_%: 20%; SizeZ_mm: 42mm; AEC Grade: Grade 2; IRMS_A: 1.75A; Value: 240µF; Leakage Current: 360uA; Life: 7000Hours; AEC Qualified: Yes; Esr: 0.8592
C37 C42 C47 C52 = CMP-0121428-1: 3.9 µF Film Capacitor 700V Polypropylene (PP), Metallized Radial; Manufacturer: TDK; AEC Qualified: No; Cap_F: 3.9µF; SizeZ_mm: 24.5mm; Tolerance_%: 10%; Value: 3.9µF
C38-C40 C43-C45 C48-C50 C53-C55 = CMP-0098327-1: 0.25 µF ±20% 500V Ceramic Capacitor 2220 (5750 Metric); Manufacturer: TDK; AEC Qualified: No; SizeZ_mm: 1.6mm; Value: 250nF
C458-C460 = CMP-0009326-2: CAP, CERM, 0.1 uF, 1000 V, +/- 10%, X7R, 1812; Manufacturer: Kemet; TaMin_C: -55°C; Polarized: N; SizeAreaWB_mm2: 23.1; Value1: Unknown; U/M: EA; Value: 0.1uF; TaMax_C: 125°C; SizeZ_mm: 2.54; SizeX_mm: 4.5; SizeY_mm: 3.2; Cap_Case: 1812; Value2: 1000V; SizeArea_mm2: 14.4; Cap_F: 100nF; AEC Category: Q200
J13 = CMP-0055799-1: Panel Socket, 24A, R/A, Gold, TH; Manufacturer: Cliff Electronic Components; CNHeader: FALSE; Gender: Female; Voltage_V: 1kV
J14 J16 J17 = CMP-0098296-2: Banana Test Connector, Socket, PCB Mount, 24 A, 1 kV, Gold Plated Contacts, Brown; Manufacturer: CLIFF Electronic Components; Current_A: 24A; Voltage_V: 1kV; AEC Qualified: No; Conn Orientation: Right Angle; Is Female: yes; SizeZ_mm: 11.6mm; Standoff Height: 0.7mm
J15 = CMP-0032023-2: Banana Jack Connector Standard Banana Solder Yellow; Manufacturer: CLIFF Electronic Components; ContactFinish: Gold; Current_A: 24A; Voltage_V: 1kV; AEC Qualified: No; Conn Orientation: Horizontal; Is Female: yes; SizeZ_mm: 12.5mm; Standoff Height: 0.7mm
J18 = CMP-0055798-1: Panel Socket, 24A, R/A, Gold, TH; Manufacturer: Cliff Electronic Components; CNHeader: FALSE; Gender: Female; Voltage_V: 1kV
J30 = CMP-0098294-2: Banana Test Connector, Socket, PCB Mount, 24 A, 1 kV, Gold Plated Contacts, Green; Manufacturer: CLIFF Electronic Components; Current_A: 24A; Voltage_V: 1kV; AEC Qualified: No; Conn Orientation: Right Angle; SizeZ_mm: 11.6mm; Standoff Height: 0.7mm
L1-L3 = CMP-0122793-1: PFC Inductor; Manufacturer: Bourns; AEC Qualified: No; Ind_H: 160µH; Isat: 30A; SizeZ_mm: 41.5mm; Value: 160uH; Test Frequency: 100kHz; Tolerance_%: 10%
Q2-Q4 Q11-Q13 = CMP-0085490-1: MOSFET, N-CH, 1200 V, 30 A, TO-247-4; Alternate Manufacturer: None; Manufacturer: Cree; VdsMax_V: 1.2kV; ChMode: Enhancement; SizeX_mm: 15.94; SizeY_mm: 5.02; Value2: 51 nC; AEC Qualified: N; Value: 1200V; Value1: ? ohm; QgTyp_nC: 51; IdsMax_A: 30A; AEC Category: Q101; SizeArea_mm2: 80.0188; SizeZ_mm: 27.97; Vgs_V: 19V; SizeAreaWB_mm2: 125.9388
Q5-Q10 = CMP-0096829-1: Silicon Carbide Power MOSFET N-Channel 650 V 37A (Tc) 150W (Tc) Through Hole TO-247-4L; Manufacturer: Wolfspeed; Number Of N Channels: 1; Drain To Source Breakdown Voltage: 650V; SizeZ_mm: 27.97mm; Turn On Delay Time: 8ns; AEC Qualified: No; Rdson45_ohm: 60m; Transconductance: 10S; Vgs_V: 19V; QgTyp_nC: 46nC @ 15V; Standoff Height: 3.97mm; Pulse Drain Current: 99A; Rthja Max: 40°C/W; Typ Forward Diode Voltage: 5.1V; TJmax_C: +175°C; Threshold Vgs Min: 1.8V; Threshold Vgs Max: 3.6V; ChMode: False; Reverse Recovery Time: 11ns; Reverse Recovery Charge: 151nC; Input Capacitace At Vds: 1020pF @ 600V; Turn Off Delay Time: 17ns
R41-R49 R51-R59 = CMP-0018695-3: RES, 510 k, 5%, 0.25 W, AEC-Q200 Grade 0, 1206; Manufacturer: Vishay-Dale; Power_W: 250mW; TempCo: 200 ppm/C; Value: 510k; EIA_Code: E24; SizeX_mm: 3.2; SizeY_mm: 1.6; SizeZ_mm: 1.35; Value2: 0.25W; SizeArea_mm2: 5.12; AEC Qualified: Y; VDC_V: 200V; AEC Category: Q200; AEC Grade: 0
R50 R60 = CMP-0120177-1: 2 mOhms ±1% 1W Chip Resistor Wide 1206 (3216 Metric), 0612 Anti-Sulfur, Automotive AEC-Q200, Current Sense, Moisture Resistant, Pulse Withstanding Metal Element; Manufacturer: Vishay; AEC Grade: Grade 0; AEC Qualified: Yes; Res_ohm: 2m; SizeZ_mm: 0.711mm; TempCo: 150ppm/°C; Value: 2m
TP29-TP34 TP59-TP62 TP65-TP67 = CMP-0003968-1: Test Point, SMT; Manufacturer: Harwin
